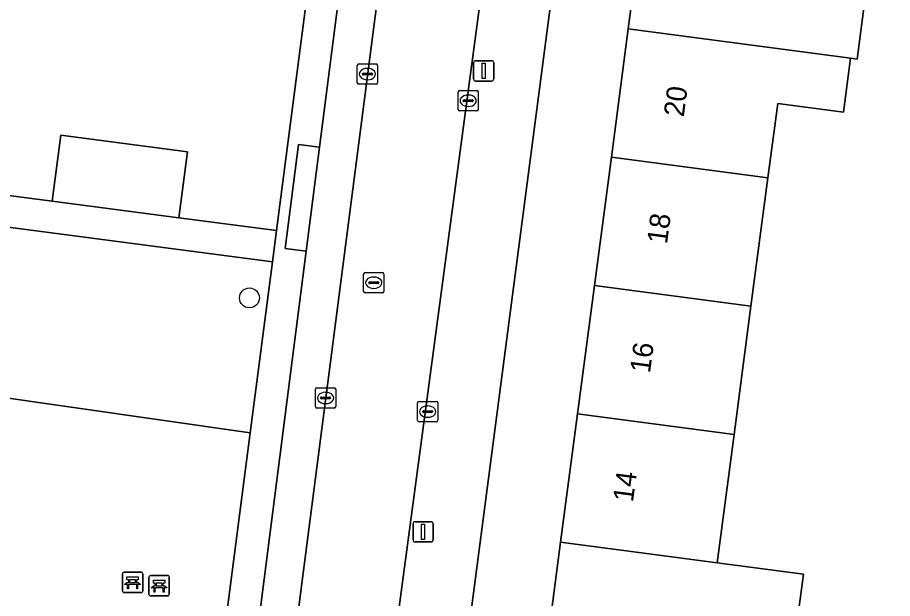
# Model space of a CAD drawing. Extents: x 162184 to 163154, y 385507 to 386516.
# Drawn here: x 162501.72 to 162544.83, y 386198.46 to 386227.08 of the extents above; entities that cross this region are included whole.
import ezdxf

# ---------------------------------------------------------------- set-up
doc = ezdxf.new("R2010")
doc.units = 0
for name, color, linetype in [('IMGEO_Bank', 7, 'Continuous'), ('IMGEO_Boom', 7, 'Continuous'), ('IMGEO_Erf', 7, 'Continuous'), ('IMGEO_Groenvoorziening', 7, 'Continuous'), ('IMGEO_Kolk', 7, 'Continuous'), ('IMGEO_Lichtmast', 7, 'Continuous'), ('IMGEO_Pand', 7, 'Continuous'), ('IMGEO_Pand_nummerreeks', 7, 'Continuous'), ('IMGEO_Parkeervlak_open', 7, 'Continuous'), ('IMGEO_Rijbaan_lokaal_open', 7, 'Continuous'), ('IMGEO_Rioolput', 7, 'Continuous'), ('IMGEO_Voetpad_open', 7, 'Continuous')]:
    doc.layers.add(name, color=color, linetype=linetype)

msp = doc.modelspace()

# ---------------------------------------------------------------- linework, layer by layer
at = {"layer": 'IMGEO_Bank'}
for p, q in [((162506.893, 386198.829), (162506.893, 386199.67)), ((162506.893, 386199.67), (162506.893, 386198.829)), ((162506.968, 386199.754), (162507.809, 386199.754)), ((162507.809, 386199.754), (162506.968, 386199.754)), ((162507.893, 386199.679), (162507.893, 386198.838)), ((162507.893, 386198.838), (162507.893, 386199.679)), ((162508.272, 386199.589), (162509.113, 386199.589)), ((162509.113, 386199.589), (162508.272, 386199.589)), ((162507.59, 386199.152), (162507.197, 386199.152)), ((162507.202, 386199.26), (162507.202, 386199.366)), ((162507.246, 386199.366), (162507.246, 386199.26)), ((162507.534, 386199.372), (162507.252, 386199.372)), ((162507.252, 386199.254), (162507.534, 386199.254)), ((162507.54, 386199.26), (162507.54, 386199.366)), ((162507.584, 386199.366), (162507.584, 386199.26)), ((162508.197, 386198.664), (162508.197, 386199.505)), ((162508.197, 386199.505), (162508.197, 386198.664)), ((162508.506, 386199.095), (162508.506, 386199.201)), ((162508.55, 386199.201), (162508.55, 386199.095)), ((162508.838, 386199.207), (162508.556, 386199.207)), ((162508.844, 386199.095), (162508.844, 386199.201)), ((162508.888, 386199.201), (162508.888, 386199.095)), ((162509.197, 386199.514), (162509.197, 386198.673)), ((162509.197, 386198.673), (162509.197, 386199.514)), ((162507.818, 386198.754), (162506.977, 386198.754)), ((162506.977, 386198.754), (162507.818, 386198.754)), ((162508.894, 386198.987), (162508.501, 386198.987)), ((162508.556, 386199.089), (162508.838, 386199.089)), ((162509.122, 386198.589), (162508.281, 386198.589)), ((162508.281, 386198.589), (162509.122, 386198.589))]:
    msp.add_line(p, q, dxfattribs=at)
for points in [[(162507.14, 386199.152), (162506.998, 386199.152), (162507.11, 386199.254), (162507.196, 386199.254)], [(162507.196, 386199.372), (162507.11, 386199.372), (162507.11, 386199.533), (162507.673, 386199.533), (162507.673, 386199.372), (162507.59, 386199.372)], [(162507.19, 386199.145), (162507.19, 386198.938), (162507.147, 386198.938), (162507.147, 386199.145)], [(162507.59, 386199.254), (162507.673, 386199.254), (162507.785, 386199.152), (162507.646, 386199.152)], [(162507.64, 386199.145), (162507.64, 386198.938), (162507.596, 386198.938), (162507.596, 386199.145)], [(162508.5, 386199.207), (162508.414, 386199.207), (162508.414, 386199.368), (162508.977, 386199.368), (162508.977, 386199.207), (162508.894, 386199.207)], [(162508.444, 386198.987), (162508.302, 386198.987), (162508.414, 386199.089), (162508.5, 386199.089)], [(162508.494, 386198.98), (162508.494, 386198.773), (162508.451, 386198.773), (162508.451, 386198.98)], [(162508.894, 386199.089), (162508.977, 386199.089), (162509.089, 386198.987), (162508.95, 386198.987)], [(162508.944, 386198.98), (162508.944, 386198.773), (162508.9, 386198.773), (162508.9, 386198.98)]]:
    msp.add_lwpolyline(points, dxfattribs=at)
for centre, radius, start, end in [((162506.971, 386199.676), 0.0779, 92.4484, 184.2845), ((162506.971, 386199.676), 0.0779, 92.4484, 184.2845), ((162507.815, 386199.676), 0.0779, 2.4484, 94.2845), ((162507.815, 386199.676), 0.0779, 2.4484, 94.2845), ((162508.275, 386199.511), 0.0779, 92.4484, 184.2845), ((162508.275, 386199.511), 0.0779, 92.4484, 184.2845), ((162509.119, 386199.511), 0.0779, 2.4484, 94.2845), ((162509.119, 386199.511), 0.0779, 2.4484, 94.2845), ((162507.14, 386199.145), 0.00671, 2.8957, 87.1043), ((162507.197, 386199.145), 0.00671, 92.8957, 177.1043), ((162507.195, 386199.365), 0.00671, 2.8957, 87.1043), ((162507.195, 386199.261), 0.00671, 272.8957, 357.1043), ((162507.252, 386199.365), 0.00671, 92.8957, 177.1043), ((162507.252, 386199.261), 0.00671, 182.8957, 267.1043), ((162507.534, 386199.365), 0.00671, 2.8957, 87.1043), ((162507.534, 386199.261), 0.00671, 272.8957, 357.1043), ((162507.591, 386199.365), 0.00671, 92.8957, 177.1043), ((162507.591, 386199.261), 0.00671, 182.8957, 267.1043), ((162507.589, 386199.145), 0.00671, 2.8957, 87.1043), ((162507.646, 386199.145), 0.00671, 92.8957, 177.1043), ((162508.499, 386199.2), 0.00671, 2.8957, 87.1043), ((162508.556, 386199.2), 0.00671, 92.8957, 177.1043), ((162508.838, 386199.2), 0.00671, 2.8957, 87.1043), ((162508.895, 386199.2), 0.00671, 92.8957, 177.1043), ((162506.971, 386198.832), 0.0779, 182.4484, 274.2845), ((162506.971, 386198.832), 0.0779, 182.4484, 274.2845), ((162507.815, 386198.832), 0.0779, 272.4484, 4.2845), ((162507.815, 386198.832), 0.0779, 272.4484, 4.2845), ((162508.444, 386198.98), 0.00671, 2.8957, 87.1043), ((162508.501, 386198.98), 0.00671, 92.8957, 177.1043), ((162508.499, 386199.096), 0.00671, 272.8957, 357.1043), ((162508.556, 386199.096), 0.00671, 182.8957, 267.1043), ((162508.838, 386199.096), 0.00671, 272.8957, 357.1043), ((162508.895, 386199.096), 0.00671, 182.8957, 267.1043), ((162508.893, 386198.98), 0.00671, 2.8957, 87.1043), ((162508.95, 386198.98), 0.00671, 92.8957, 177.1043), ((162508.275, 386198.667), 0.0779, 182.4484, 274.2845), ((162508.275, 386198.667), 0.0779, 182.4484, 274.2845), ((162509.119, 386198.667), 0.0779, 272.4484, 4.2845), ((162509.119, 386198.667), 0.0779, 272.4484, 4.2845)]:
    msp.add_arc(centre, radius, start, end, dxfattribs=at)
at = {"layer": 'IMGEO_Boom'}
msp.add_circle((162513.148, 386213.268), 0.489, dxfattribs=at)
at = {"layer": 'IMGEO_Erf'}
for points in [[(162527.645, 386194.92), (162528.478, 386201.239), (162529.311, 386207.559), (162530.145, 386213.881), (162530.978, 386220.201), (162531.811, 386226.521), (162532.644, 386232.841), (162533.477, 386239.162), (162534.331, 386245.637), (162535.367, 386245.5), (162535.595, 386247.298), (162535.993, 386250.436), (162536.392, 386253.575), (162536.591, 386255.142)], [(162527.746, 386251.794), (162529.167, 386250), (162530.299, 386247.954), (162530.386, 386246.165), (162518.722, 386156.946)], [(162549.689, 386245.409), (162544.758, 386246.095), (162544.521, 386244.293), (162542.042, 386244.62), (162541.188, 386238.144), (162544.39, 386237.72), (162543.557, 386231.4), (162543.913, 386231.353), (162543.08, 386225.032), (162542.761, 386225.074), (162542.409, 386222.412), (162539.171, 386222.84), (162538.688, 386219.182), (162537.855, 386212.863), (162537.022, 386206.54), (162536.189, 386200.22), (162540.447, 386199.659), (162540.074, 386196.836)], [(162499.127, 386233.263), (162492.958, 386234.079), (162486.486, 386234.935), (162480.216, 386235.765), (162473.616, 386236.638), (162472.041, 386224.64), (162478.634, 386223.787), (162478.776, 386224.885), (162481.884, 386224.483), (162481.771, 386223.608), (162484.936, 386223.199), (162488.308, 386222.762), (162487.957, 386220.049), (162493.695, 386219.301), (162494.028, 386221.855), (162497.559, 386221.394), (162501.108, 386220.931), (162500.775, 386218.377), (162503.434, 386218.031), (162503.86, 386221.286), (162510.101, 386220.469), (162509.675, 386217.215), (162514.479, 386216.591), (162517.483, 386239.714)]]:
    msp.add_lwpolyline(points, dxfattribs=at)
at = {"layer": 'IMGEO_Groenvoorziening'}
for points in [[(162513.182, 386206.613), (162514.278, 386215.046), (162500, 386216.916), (162484.192, 386218.986), (162483.129, 386210.95), (162484.688, 386210.725), (162500, 386208.516)], [(162513.182, 386206.613), (162500, 386208.516), (162484.688, 386210.725), (162483.129, 386210.95), (162482.938, 386209.506), (162482.206, 386203.964), (162481.835, 386201.154), (162473.483, 386202.26), (162474.138, 386207.216), (162468.483, 386207.962), (162467.503, 386198.971), (162453.471, 386201.1), (162452.471, 386193.504), (162500.008, 386187.3), (162500.62, 386192.004), (162511.108, 386190.65)]]:
    msp.add_lwpolyline(points, close=True, dxfattribs=at)
at = {"layer": 'IMGEO_Kolk'}
for p, q in [((162518.46, 386223.868), (162518.46, 386224.72)), ((162518.535, 386224.794), (162519.387, 386224.794)), ((162518.948, 386224.574), (162518.973, 386224.574)), ((162519.461, 386224.72), (162519.461, 386223.868)), ((162518.719, 386224.288), (162518.719, 386224.3)), ((162519.157, 386224.251), (162518.759, 386224.251)), ((162518.762, 386224.337), (162519.16, 386224.337)), ((162519.203, 386224.3), (162519.203, 386224.288)), ((162519.387, 386223.794), (162518.535, 386223.794)), ((162518.971, 386224.014), (162518.946, 386224.014)), ((162523.423, 386222.554), (162523.423, 386223.406)), ((162523.498, 386223.48), (162524.35, 386223.48)), ((162523.911, 386223.26), (162523.936, 386223.26)), ((162524.424, 386223.406), (162524.424, 386222.554)), ((162523.682, 386222.974), (162523.682, 386222.986)), ((162524.12, 386222.937), (162523.722, 386222.937)), ((162523.725, 386223.023), (162524.123, 386223.023)), ((162524.166, 386222.986), (162524.166, 386222.974)), ((162524.35, 386222.48), (162523.498, 386222.48)), ((162523.934, 386222.7), (162523.909, 386222.7)), ((162516.397, 386207.913), (162516.397, 386208.765)), ((162516.472, 386208.839), (162517.324, 386208.839)), ((162516.885, 386208.619), (162516.91, 386208.619)), ((162517.398, 386208.765), (162517.398, 386207.913)), ((162516.656, 386208.333), (162516.656, 386208.345)), ((162517.094, 386208.296), (162516.696, 386208.296)), ((162516.699, 386208.382), (162517.097, 386208.382)), ((162517.14, 386208.345), (162517.14, 386208.333)), ((162517.324, 386207.839), (162516.472, 386207.839)), ((162516.908, 386208.059), (162516.883, 386208.059)), ((162521.427, 386207.239), (162521.427, 386208.091)), ((162521.502, 386208.165), (162522.354, 386208.165)), ((162521.915, 386207.945), (162521.94, 386207.945)), ((162522.428, 386208.091), (162522.428, 386207.239)), ((162521.686, 386207.659), (162521.686, 386207.671)), ((162522.124, 386207.622), (162521.726, 386207.622)), ((162521.729, 386207.708), (162522.127, 386207.708)), ((162521.938, 386207.385), (162521.913, 386207.385)), ((162522.17, 386207.671), (162522.17, 386207.659)), ((162522.354, 386207.165), (162521.502, 386207.165))]:
    msp.add_line(p, q, dxfattribs=at)
for points in [[(162518.46, 386223.868), (162518.46, 386224.72)], [(162518.535, 386224.794), (162519.387, 386224.794)], [(162519.461, 386224.72), (162519.461, 386223.868)], [(162519.387, 386223.794), (162518.535, 386223.794)], [(162523.423, 386222.554), (162523.423, 386223.406)], [(162523.498, 386223.48), (162524.35, 386223.48)], [(162524.424, 386223.406), (162524.424, 386222.554)], [(162524.35, 386222.48), (162523.498, 386222.48)], [(162516.397, 386207.913), (162516.397, 386208.765)], [(162516.472, 386208.839), (162517.324, 386208.839)], [(162517.398, 386208.765), (162517.398, 386207.913)], [(162517.324, 386207.839), (162516.472, 386207.839)], [(162521.427, 386207.239), (162521.427, 386208.091)], [(162521.502, 386208.165), (162522.354, 386208.165)], [(162522.428, 386208.091), (162522.428, 386207.239)], [(162522.354, 386207.165), (162521.502, 386207.165)]]:
    msp.add_lwpolyline(points, dxfattribs=at)
for centre, radius, start, end in [((162518.537, 386224.718), 0.0765, 91.552, 178.448), ((162518.537, 386224.718), 0.0765, 91.552, 178.448), ((162519.385, 386224.718), 0.0765, 1.552, 88.448), ((162519.385, 386224.718), 0.0765, 1.552, 88.448), ((162518.759, 386224.297), 0.0403, 85.8775, 175.7526), ((162518.756, 386224.287), 0.0366, 178.938, 274.7102), ((162519.16, 386224.294), 0.043, 264.8664, 352.4533), ((162519.164, 386224.299), 0.0386, 1.7309, 96.639), ((162518.537, 386223.87), 0.0765, 181.552, 268.448), ((162518.537, 386223.87), 0.0765, 181.552, 268.448), ((162519.385, 386223.87), 0.0765, 271.552, 358.448), ((162519.385, 386223.87), 0.0765, 271.552, 358.448), ((162523.5, 386223.404), 0.0765, 91.552, 178.448), ((162523.5, 386223.404), 0.0765, 91.552, 178.448), ((162524.348, 386223.404), 0.0765, 1.552, 88.448), ((162524.348, 386223.404), 0.0765, 1.552, 88.448), ((162523.722, 386222.983), 0.0403, 85.8775, 175.7526), ((162523.719, 386222.973), 0.0366, 178.938, 274.7102), ((162524.123, 386222.98), 0.043, 264.8664, 352.4533), ((162524.127, 386222.985), 0.0386, 1.7309, 96.639), ((162523.5, 386222.556), 0.0765, 181.552, 268.448), ((162523.5, 386222.556), 0.0765, 181.552, 268.448), ((162524.348, 386222.556), 0.0765, 271.552, 358.448), ((162524.348, 386222.556), 0.0765, 271.552, 358.448), ((162516.474, 386208.763), 0.0765, 91.552, 178.448), ((162516.474, 386208.763), 0.0765, 91.552, 178.448), ((162517.322, 386208.763), 0.0765, 1.552, 88.448), ((162517.322, 386208.763), 0.0765, 1.552, 88.448), ((162516.696, 386208.342), 0.0403, 85.8775, 175.7526), ((162516.693, 386208.332), 0.0366, 178.938, 274.7102), ((162517.097, 386208.339), 0.043, 264.8664, 352.4533), ((162517.101, 386208.344), 0.0386, 1.7309, 96.639), ((162516.474, 386207.915), 0.0765, 181.552, 268.448), ((162516.474, 386207.915), 0.0765, 181.552, 268.448), ((162517.322, 386207.915), 0.0765, 271.552, 358.448), ((162517.322, 386207.915), 0.0765, 271.552, 358.448), ((162521.504, 386208.089), 0.0765, 91.552, 178.448), ((162521.504, 386208.089), 0.0765, 91.552, 178.448), ((162522.352, 386208.089), 0.0765, 1.552, 88.448), ((162522.352, 386208.089), 0.0765, 1.552, 88.448), ((162521.726, 386207.668), 0.0403, 85.8775, 175.7526), ((162521.723, 386207.658), 0.0366, 178.938, 274.7102), ((162522.127, 386207.665), 0.043, 264.8664, 352.4533), ((162522.131, 386207.67), 0.0386, 1.7309, 96.639), ((162521.504, 386207.241), 0.0765, 181.552, 268.448), ((162521.504, 386207.241), 0.0765, 181.552, 268.448), ((162522.352, 386207.241), 0.0765, 271.552, 358.448), ((162522.352, 386207.241), 0.0765, 271.552, 358.448)]:
    msp.add_arc(centre, radius, start, end, dxfattribs=at)
for centre, major_axis, ratio, start_param, end_param in [((162518.947, 386224.294), (-0.387, 0.002), 0.722429, 4.712389, 7.853982), ((162518.972, 386224.294), (-0.39, 0.002), 0.717154, 1.570796, 4.712389), ((162523.91, 386222.98), (-0.387, 0.002), 0.722429, 4.712389, 7.853982), ((162523.935, 386222.98), (-0.39, 0.002), 0.717154, 1.570796, 4.712389), ((162516.884, 386208.339), (-0.387, 0.002), 0.722429, 4.712389, 7.853982), ((162516.909, 386208.339), (-0.39, 0.002), 0.717154, 1.570796, 4.712389), ((162521.914, 386207.665), (-0.387, 0.002), 0.722429, 4.712389, 7.853982), ((162521.939, 386207.665), (-0.39, 0.002), 0.717154, 1.570796, 4.712389)]:
    msp.add_ellipse(centre, major_axis=major_axis, ratio=ratio, start_param=start_param, end_param=end_param, dxfattribs=at)
at = {"layer": 'IMGEO_Lichtmast'}
for p, q in [((162524.191, 386224.052), (162524.191, 386224.852)), ((162524.191, 386224.852), (162524.191, 386224.052)), ((162524.291, 386224.952), (162525.081, 386224.952)), ((162525.081, 386224.952), (162524.291, 386224.952)), ((162525.181, 386224.852), (162525.181, 386224.052)), ((162525.181, 386224.052), (162525.181, 386224.852)), ((162525.081, 386223.952), (162524.291, 386223.952)), ((162524.291, 386223.952), (162525.081, 386223.952)), ((162521.207, 386201.344), (162521.207, 386202.144)), ((162521.207, 386202.144), (162521.207, 386201.344)), ((162521.307, 386202.244), (162522.097, 386202.244)), ((162522.097, 386202.244), (162521.307, 386202.244)), ((162522.197, 386202.144), (162522.197, 386201.344)), ((162522.197, 386201.344), (162522.197, 386202.144)), ((162522.097, 386201.244), (162521.307, 386201.244)), ((162521.307, 386201.244), (162522.097, 386201.244))]:
    msp.add_line(p, q, dxfattribs=at)
for points in [[(162524.611, 386224.827), (162524.761, 386224.827), (162524.761, 386224.077), (162524.611, 386224.077), (162524.611, 386224.827)], [(162521.627, 386202.119), (162521.777, 386202.119), (162521.777, 386201.369), (162521.627, 386201.369), (162521.627, 386202.119)]]:
    msp.add_lwpolyline(points, dxfattribs=at)
for centre, start, end in [((162524.291, 386224.852), 90, 180), ((162524.291, 386224.852), 90, 180), ((162525.081, 386224.852), 0, 90), ((162525.081, 386224.852), 360, 90), ((162524.291, 386224.052), 180, 270), ((162524.291, 386224.052), 180, 270), ((162525.081, 386224.052), 270, 0), ((162525.081, 386224.052), 270, 0), ((162521.307, 386202.144), 90, 180), ((162521.307, 386202.144), 90, 180), ((162522.097, 386202.144), 0, 90), ((162522.097, 386202.144), 360, 90), ((162521.307, 386201.344), 180, 270), ((162521.307, 386201.344), 180, 270), ((162522.097, 386201.344), 270, 0), ((162522.097, 386201.344), 270, 0)]:
    msp.add_arc(centre, 0.1, start, end, dxfattribs=at)
at = {"layer": 'IMGEO_Pand'}
for points in [[(162543.913, 386231.353), (162543.557, 386231.4), (162540.355, 386231.822), (162532.644, 386232.841), (162531.811, 386226.521), (162539.522, 386225.502), (162542.761, 386225.074), (162543.08, 386225.032)], [(162539.171, 386222.84), (162542.409, 386222.412), (162542.761, 386225.074), (162539.522, 386225.502), (162531.811, 386226.521), (162530.978, 386220.201), (162538.688, 386219.182)], [(162510.101, 386220.469), (162503.86, 386221.286), (162503.434, 386218.031), (162509.675, 386217.215)], [(162537.855, 386212.863), (162538.688, 386219.182), (162530.978, 386220.201), (162530.145, 386213.881)], [(162530.145, 386213.881), (162529.311, 386207.559), (162537.022, 386206.54), (162537.855, 386212.863)], [(162529.311, 386207.559), (162528.478, 386201.239), (162536.189, 386200.22), (162537.022, 386206.54)], [(162538.053, 386197.103), (162540.074, 386196.836), (162540.447, 386199.659), (162536.189, 386200.22), (162528.478, 386201.239), (162527.645, 386194.92), (162537.591, 386193.606)]]:
    msp.add_lwpolyline(points, close=True, dxfattribs=at)
at = {"layer": 'IMGEO_Parkeervlak_open'}
for points in [[(162514.746, 386191.574), (162520.569, 386236.666)], [(162518.321, 386234.121), (162516.6, 386220.687), (162515.946, 386215.576), (162513.185, 386194.022)]]:
    msp.add_lwpolyline(points, dxfattribs=at)
at = {"layer": 'IMGEO_Rijbaan_lokaal_open'}
msp.add_lwpolyline([(162514.645, 386152.313), (162515.183, 386156.42), (162517.587, 386175.419), (162518.419, 386181.789), (162519.542, 386190.566), (162519.686, 386191.776), (162525.592, 386235.986), (162520.569, 386236.666), (162514.746, 386191.574), (162514.616, 386190.567)], dxfattribs=at)
at = {"layer": 'IMGEO_Rioolput'}
for p, q in [((162518.773, 386213.59), (162518.773, 386214.442)), ((162518.848, 386214.516), (162519.7, 386214.516)), ((162519.261, 386214.296), (162519.286, 386214.296)), ((162519.774, 386214.442), (162519.774, 386213.59)), ((162519.032, 386214.01), (162519.032, 386214.022)), ((162519.47, 386213.973), (162519.072, 386213.973)), ((162519.075, 386214.059), (162519.473, 386214.059)), ((162519.516, 386214.022), (162519.516, 386214.01)), ((162519.7, 386213.516), (162518.848, 386213.516)), ((162519.284, 386213.736), (162519.259, 386213.736))]:
    msp.add_line(p, q, dxfattribs=at)
for points in [[(162518.773, 386213.59), (162518.773, 386214.442)], [(162518.848, 386214.516), (162519.7, 386214.516)], [(162519.774, 386214.442), (162519.774, 386213.59)], [(162519.7, 386213.516), (162518.848, 386213.516)]]:
    msp.add_lwpolyline(points, dxfattribs=at)
for centre, radius, start, end in [((162518.85, 386214.44), 0.0765, 91.552, 178.448), ((162518.85, 386214.44), 0.0765, 91.552, 178.448), ((162519.698, 386214.44), 0.0765, 1.552, 88.448), ((162519.698, 386214.44), 0.0765, 1.552, 88.448), ((162519.072, 386214.019), 0.0403, 85.8775, 175.7526), ((162519.069, 386214.009), 0.0366, 178.938, 274.7102), ((162519.473, 386214.016), 0.043, 264.8664, 352.4533), ((162519.477, 386214.021), 0.0386, 1.7309, 96.639), ((162518.85, 386213.592), 0.0765, 181.552, 268.448), ((162518.85, 386213.592), 0.0765, 181.552, 268.448), ((162519.698, 386213.592), 0.0765, 271.552, 358.448), ((162519.698, 386213.592), 0.0765, 271.552, 358.448)]:
    msp.add_arc(centre, radius, start, end, dxfattribs=at)
for centre, major_axis, ratio, start_param, end_param in [((162519.26, 386214.016), (-0.387, 0.002), 0.722429, 4.712389, 7.853982), ((162519.285, 386214.016), (-0.39, 0.002), 0.717154, 1.570796, 4.712389)]:
    msp.add_ellipse(centre, major_axis=major_axis, ratio=ratio, start_param=start_param, end_param=end_param, dxfattribs=at)
at = {"layer": 'IMGEO_Voetpad_open'}
for points in [[(162518.534, 386155.508), (162518.722, 386156.946), (162530.386, 386246.165), (162530.299, 386247.954), (162529.167, 386250), (162527.746, 386251.794)], [(162519.489, 386241.838), (162517.483, 386239.714), (162514.479, 386216.591), (162514.278, 386215.046), (162513.182, 386206.613), (162511.108, 386190.65), (162510.792, 386188.743), (162512.043, 386186.234)], [(162525.867, 386238.045), (162525.592, 386235.986), (162519.686, 386191.776), (162519.542, 386190.566), (162520.721, 386190.459), (162519.569, 386181.682), (162518.419, 386181.789), (162517.587, 386175.419), (162515.183, 386156.42), (162516.222, 386156.271), (162515.686, 386152.177), (162514.645, 386152.313), (162511.491, 386128.213)], [(162513.185, 386194.022), (162515.946, 386215.576), (162514.905, 386215.709), (162515.56, 386220.832), (162516.6, 386220.687), (162518.321, 386234.121)], [(162500, 386216.916), (162514.278, 386215.046), (162514.479, 386216.591), (162509.675, 386217.215), (162503.434, 386218.031), (162500.775, 386218.377)]]:
    msp.add_lwpolyline(points, dxfattribs=at)
msp.add_lwpolyline([(162515.946, 386215.576), (162516.6, 386220.687), (162515.56, 386220.832), (162514.905, 386215.709)], close=True, dxfattribs=at)

# ---------------------------------------------------------------- texts
at = {"layer": 'IMGEO_Pand_nummerreeks'}
for s, p in [('20', (162534.543, 386222.153)), ('18', (162533.718, 386215.889)), ('16', (162532.879, 386209.532)), ('14', (162532.041, 386203.178))]:
    msp.add_text(s, height=1, rotation=82.4898, dxfattribs=at).set_placement(p)

doc.saveas('drawing.dxf')
